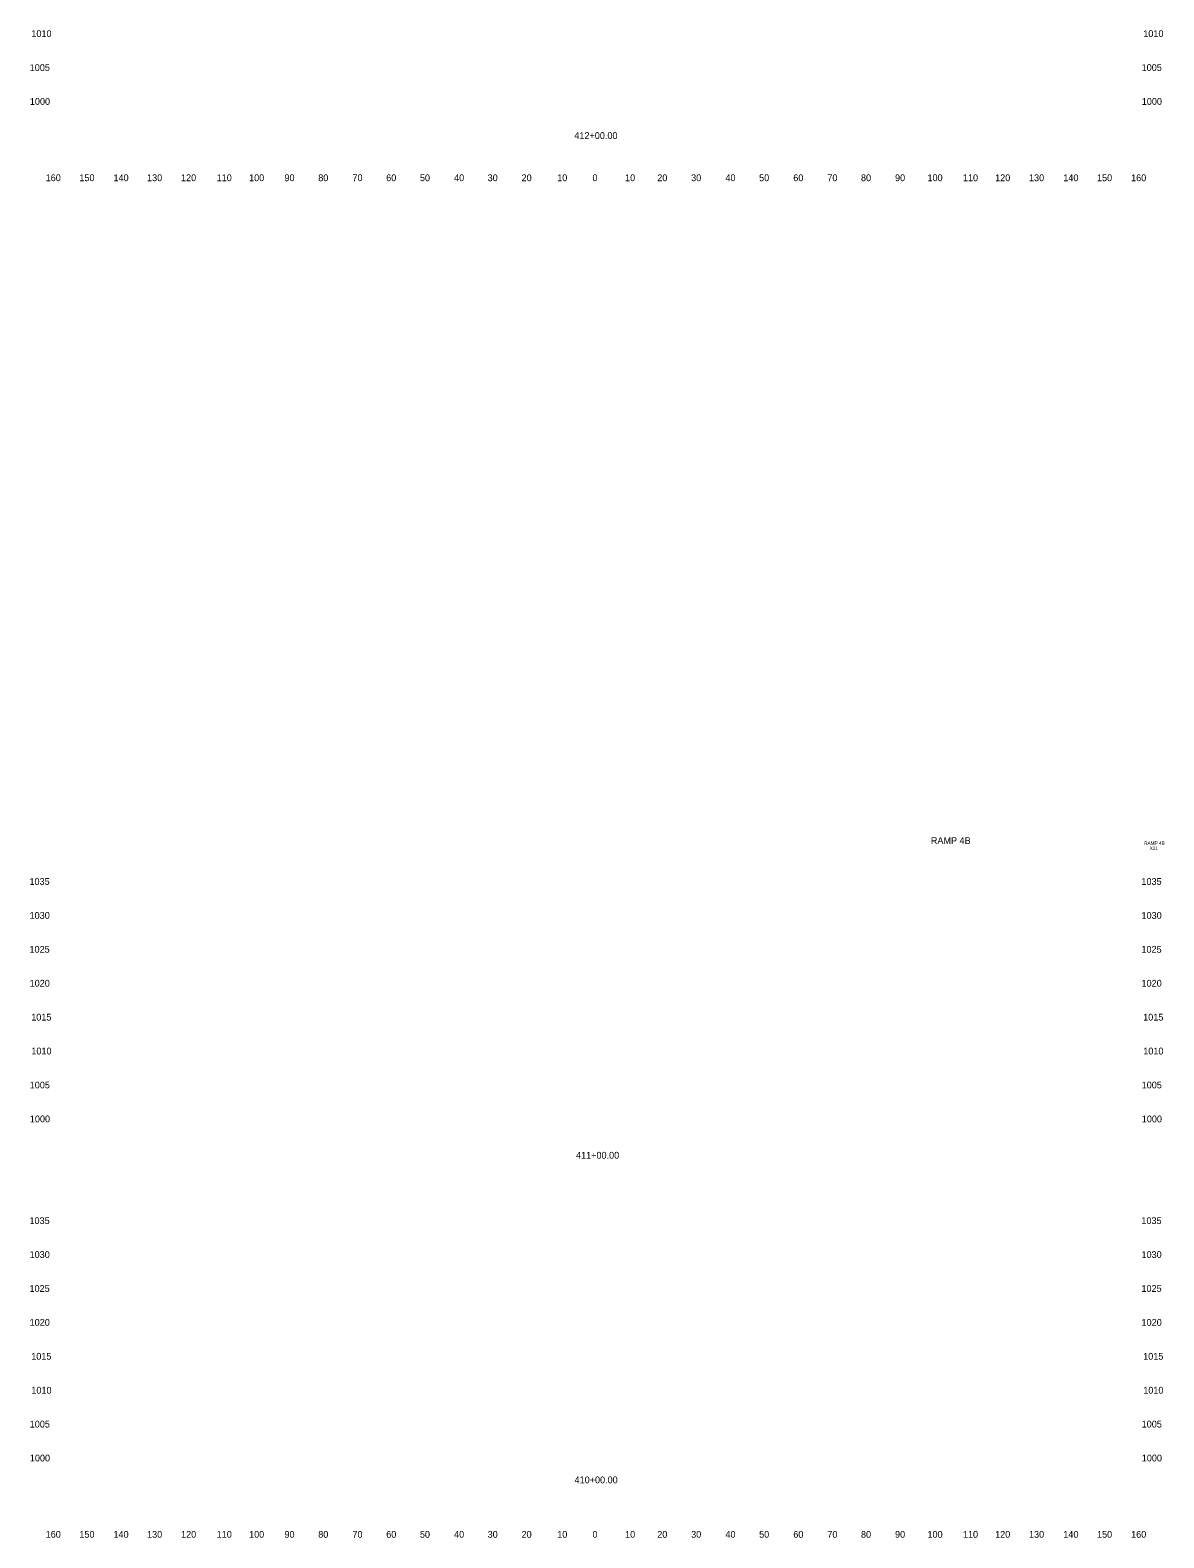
# Model space of a CAD drawing. Extents: x 4994 to 6358, y 4997 to 8804.
# Drawn here: x 6023.5 to 6357.7, y 4997.5 to 5442 of the extents above; entities that cross this region are included whole.
import ezdxf

# ---------------------------------------------------------------- set-up
doc = ezdxf.new("R2010")
doc.units = 0
for name, color, linetype in [('CLS_Search_Dist', 7, 'Continuous'), ('RD_XE_Ground', 7, 'Continuous'), ('UC_PD_Text', 7, 'Continuous')]:
    doc.layers.add(name, color=color, linetype=linetype)

msp = doc.modelspace()

# ---------------------------------------------------------------- texts
at = {"layer": 'CLS_Search_Dist'}
for s, p in [('1010', (6023.88, 5440)), ('1010', (6351.68, 5440)), ('1005', (6023.4, 5430)), ('1005', (6351.2, 5430)), ('1000', (6023.44, 5420)), ('1000', (6351.24, 5420)), ('160', (6028.1, 5397.5)), ('150', (6038.04, 5397.5)), ('140', (6048.1, 5397.5)), ('130', (6057.99, 5397.5)), ('120', (6068.01, 5397.5)), ('110', (6078.51, 5397.5)), ('100', (6088.07, 5397.5)), ('90', (6098.5, 5397.5)), ('80', (6108.46, 5397.5)), ('70', (6118.54, 5397.5)), ('60', (6128.5, 5397.5)), ('50', (6138.43, 5397.5)), ('40', (6148.5, 5397.5)), ('30', (6158.39, 5397.5)), ('20', (6168.4, 5397.5)), ('10', (6178.91, 5397.5)), ('0', (6189.3, 5397.5)), ('0', (6189.3, 5397.5)), ('10', (6198.91, 5397.5)), ('20', (6208.4, 5397.5)), ('30', (6218.39, 5397.5)), ('40', (6228.5, 5397.5)), ('50', (6238.43, 5397.5)), ('60', (6248.5, 5397.5)), ('70', (6258.54, 5397.5)), ('80', (6268.46, 5397.5)), ('90', (6278.5, 5397.5)), ('100', (6288.07, 5397.5)), ('110', (6298.51, 5397.5)), ('120', (6308.01, 5397.5)), ('130', (6317.99, 5397.5)), ('140', (6328.1, 5397.5)), ('150', (6338.04, 5397.5)), ('160', (6348.1, 5397.5)), ('1035', (6023.33, 5190)), ('1035', (6351.13, 5190)), ('1030', (6023.36, 5180)), ('1030', (6351.16, 5180)), ('1025', (6023.34, 5170)), ('1025', (6351.14, 5170)), ('1020', (6023.37, 5160)), ('1020', (6351.17, 5160)), ('1015', (6023.85, 5150)), ('1015', (6351.65, 5150)), ('1010', (6023.88, 5140)), ('1010', (6351.68, 5140)), ('1005', (6023.4, 5130)), ('1005', (6351.2, 5130)), ('1000', (6023.44, 5120)), ('1000', (6351.24, 5120)), ('1035', (6023.33, 5090)), ('1035', (6351.13, 5090)), ('1030', (6023.36, 5080)), ('1030', (6351.16, 5080)), ('1025', (6023.34, 5070)), ('1025', (6351.14, 5070)), ('1020', (6023.37, 5060)), ('1020', (6351.17, 5060)), ('1015', (6023.85, 5050)), ('1015', (6351.65, 5050)), ('1010', (6023.88, 5040)), ('1010', (6351.68, 5040)), ('1005', (6023.4, 5030)), ('1005', (6351.2, 5030)), ('1000', (6023.44, 5020)), ('1000', (6351.24, 5020)), ('160', (6028.1, 4997.5)), ('150', (6038.04, 4997.5)), ('140', (6048.1, 4997.5)), ('130', (6057.99, 4997.5)), ('120', (6068.01, 4997.5)), ('110', (6078.51, 4997.5)), ('100', (6088.07, 4997.5)), ('90', (6098.5, 4997.5)), ('80', (6108.46, 4997.5)), ('70', (6118.54, 4997.5)), ('60', (6128.5, 4997.5)), ('50', (6138.43, 4997.5)), ('40', (6148.5, 4997.5)), ('30', (6158.39, 4997.5)), ('20', (6168.4, 4997.5)), ('10', (6178.91, 4997.5)), ('0', (6189.3, 4997.5)), ('0', (6189.3, 4997.5)), ('10', (6198.91, 4997.5)), ('20', (6208.4, 4997.5)), ('30', (6218.39, 4997.5)), ('40', (6228.5, 4997.5)), ('50', (6238.43, 4997.5)), ('60', (6248.5, 4997.5)), ('70', (6258.54, 4997.5)), ('80', (6268.46, 4997.5)), ('90', (6278.5, 4997.5)), ('100', (6288.07, 4997.5)), ('110', (6298.51, 4997.5)), ('120', (6308.01, 4997.5)), ('130', (6317.99, 4997.5)), ('140', (6328.1, 4997.5)), ('150', (6338.04, 4997.5)), ('160', (6348.1, 4997.5))]:
    msp.add_text(s, height=2, dxfattribs=at).set_placement(p)
at = {"layer": 'RD_XE_Ground'}
for s, p in [('412+00.00', (6183.96, 5409.94)), ('411+00.00', (6184.46, 5109.29)), ('410+00.00', (6184.02, 5013.57))]:
    msp.add_text(s, height=2, dxfattribs=at).set_placement(p)
at = {"layer": 'UC_PD_Text'}
for s, height, p in [('RAMP 4B', 2, (6289.05, 5202.06)), ('RAMP 4B', 1, (6351.94, 5201.8)), ('X21', 1, (6353.57, 5200.3))]:
    msp.add_text(s, height=height, dxfattribs=at).set_placement(p)

doc.saveas('drawing.dxf')
